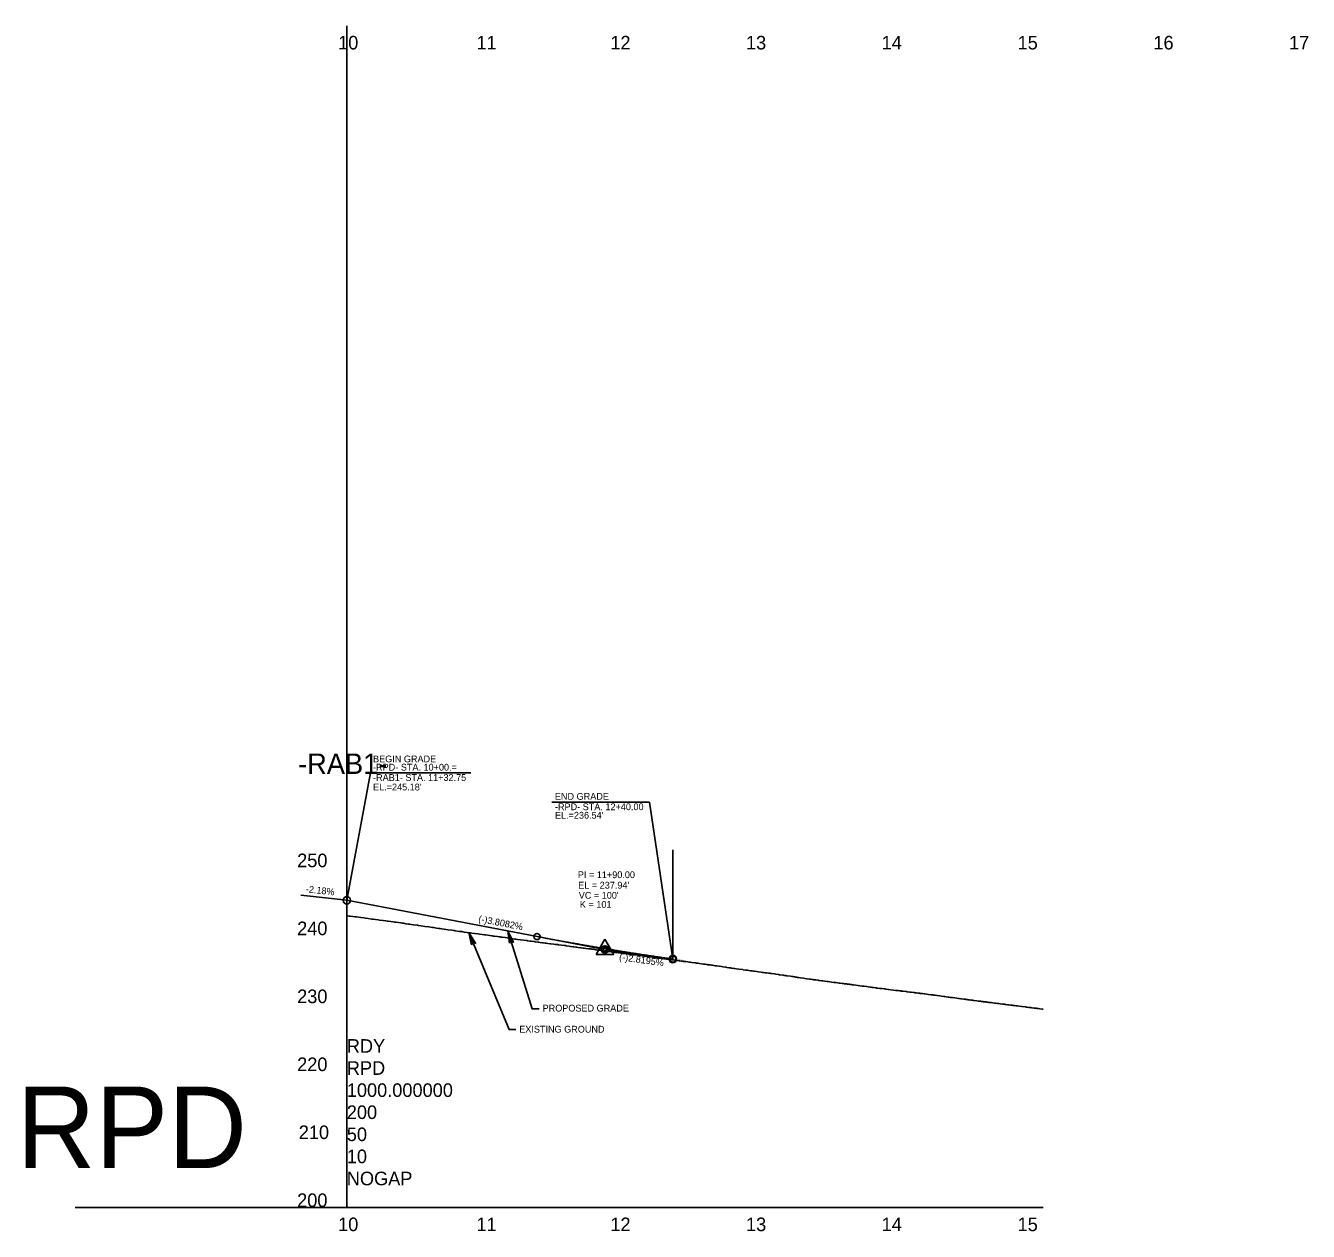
# Model space of a CAD drawing. Extents: x 2115752 to 2121174, y 562881 to 567245.
# Drawn here: x 2116460 to 2117404, y 562881 to 563768 of the extents above; entities that cross this region are included whole.
import ezdxf

# ---------------------------------------------------------------- set-up
doc = ezdxf.new("R2010")
doc.units = 0
for name, color, linetype in [('Exist Profile Cell', 7, 'Continuous'), ('Exist Vertical Profile Ground Line', 7, 'Continuous'), ('Exist Vertical Profile Horizontal Axis Label Major', 7, 'Continuous'), ('Exist Vertical Profile Vertical Axis Label', 7, 'Continuous'), ('Prop PFL VPI Symbol CELL', 7, 'Continuous'), ('Prop Terminator CELL', 7, 'Continuous'), ('Prop Vertical Profile Curve Label', 7, 'Continuous'), ('Prop Vertical Profile Grade', 7, 'Continuous'), ('Prop Vertical Profile Grade Label', 7, 'Continuous'), ('Prop VPI Label', 7, 'Continuous'), ('Scratch_Level_1', 7, 'Continuous')]:
    doc.layers.add(name, color=color, linetype=linetype)

msp = doc.modelspace()

# ---------------------------------------------------------------- linework, layer by layer
at = {"layer": 'Exist Profile Cell'}
for q in [(2116696.3, 563148.24), (2117208.79, 562898.24), (2116696.3, 562898.24)]:
    msp.add_line((2116696.3, 562898.24), q, dxfattribs=at)
at = {"layer": 'Exist Vertical Profile Ground Line'}
for points in [[(2116696.3, 563112.69), (2116696.97, 563112.62), (2116697.97, 563112.52), (2116698.83, 563112.41), (2116700.77, 563112.23), (2116702.56, 563112.03), (2116703.55, 563111.93), (2116706.51, 563111.61), (2116709.14, 563111.23), (2116710.02, 563111.11), (2116712.1, 563110.81), (2116714.73, 563110.39), (2116715.61, 563110.24), (2116717.51, 563109.95), (2116719.34, 563109.69), (2116720.3, 563109.56), (2116723.09, 563109.2), (2116724.94, 563108.97), (2116725.89, 563108.85), (2116726.81, 563108.74), (2116728.68, 563108.51), (2116730.53, 563108.25), (2116731.47, 563108.13), (2116732.38, 563108.01), (2116734.26, 563107.76), (2116736.13, 563107.48), (2116737.06, 563107.35), (2116737.99, 563107.22), (2116739.85, 563106.95), (2116741.71, 563106.69), (2116742.64, 563106.56), (2116743.59, 563106.42), (2116745.45, 563106.15), (2116748.23, 563105.75), (2116749.17, 563105.62), (2116751.07, 563105.35), (2116753.81, 563104.96), (2116756.65, 563104.56), (2116759.4, 563104.17), (2116760.35, 563104.03), (2116762.29, 563103.75), (2116764.1, 563103.49), (2116764.98, 563103.36), (2116765.96, 563103.21), (2116767.97, 563102.93), (2116770.57, 563102.54), (2116773.49, 563102.11), (2116775.28, 563101.86), (2116776.15, 563101.73), (2116779.14, 563101.31), (2116780.86, 563101.08), (2116781.74, 563100.95), (2116782.74, 563100.81), (2116784.79, 563100.52), (2116787.32, 563100.18), (2116788.33, 563100.04), (2116790.4, 563099.75), (2116792.91, 563099.41), (2116793.93, 563099.27), (2116795.99, 563098.99), (2116797.65, 563098.75), (2116798.49, 563098.63), (2116801.56, 563098.21), (2116803.25, 563097.98), (2116804.07, 563097.86), (2116805.11, 563097.72), (2116807.2, 563097.42), (2116808.84, 563097.2), (2116809.66, 563097.08), (2116810.71, 563096.94), (2116812.79, 563096.67), (2116814.44, 563096.44), (2116815.24, 563096.33), (2116817.61, 563096), (2116818.43, 563095.88), (2116820.03, 563095.65), (2116820.83, 563095.54), (2116821.9, 563095.38), (2116824.06, 563095.1), (2116826.42, 563094.79), (2116828.74, 563094.47), (2116829.34, 563094.39), (2116829.65, 563094.35), (2116831.22, 563094.14), (2116832.01, 563094.03), (2116834.27, 563093.74), (2116834.94, 563093.66), (2116835.28, 563093.61), (2116836.81, 563093.42), (2116837.6, 563093.31), (2116838.69, 563093.17), (2116840.37, 563092.96), (2116840.87, 563092.89), (2116842.4, 563092.69), (2116843.16, 563092.6), (2116844.27, 563092.45), (2116845.98, 563092.24), (2116846.49, 563092.17), (2116848.73, 563091.89), (2116849.85, 563091.75), (2116851.72, 563091.51)], [(2116851.72, 563091.51), (2116852.1, 563091.46), (2116854.34, 563091.19), (2116856.6, 563090.91), (2116857.34, 563090.82), (2116857.7, 563090.77), (2116859.95, 563090.44), (2116861.07, 563090.26), (2116862.94, 563089.96), (2116863.34, 563089.9), (2116864.79, 563089.67), (2116865.51, 563089.57), (2116866.64, 563089.41), (2116868.49, 563089.14), (2116868.93, 563089.08), (2116870.35, 563088.92), (2116871.05, 563088.83), (2116872.22, 563088.72), (2116874.09, 563088.54), (2116874.55, 563088.49), (2116875.96, 563088.36), (2116876.67, 563088.28), (2116877.84, 563088.13), (2116879.71, 563087.82), (2116880.17, 563087.76), (2116882.26, 563087.46), (2116884.3, 563087.19), (2116885.03, 563087.09), (2116885.78, 563086.98), (2116887.14, 563086.78), (2116887.45, 563086.73), (2116887.83, 563086.68), (2116889.01, 563086.52), (2116890.88, 563086.25), (2116891.35, 563086.18), (2116892.75, 563086), (2116893.45, 563085.9), (2116893.94, 563085.83), (2116894.61, 563085.74), (2116896.24, 563085.51), (2116896.88, 563085.42), (2116897.19, 563085.38), (2116898.31, 563085.21), (2116899.04, 563085.11), (2116900.43, 563084.92), (2116902.04, 563084.74), (2116902.36, 563084.7), (2116903.68, 563084.55), (2116904.7, 563084.44), (2116907.18, 563084.11), (2116907.8, 563084.03), (2116910.32, 563083.67), (2116913.42, 563083.27), (2116915.96, 563082.94), (2116916.66, 563082.86), (2116919.08, 563082.55), (2116919.91, 563082.44), (2116921.63, 563082.21), (2116922.4, 563082.11), (2116923.15, 563082.02), (2116923.85, 563081.94), (2116924.48, 563081.86), (2116926.1, 563081.65), (2116926.4, 563081.61), (2116927.31, 563081.49), (2116927.95, 563081.4), (2116929.17, 563081.25), (2116929.79, 563081.16), (2116930.11, 563081.12), (2116931.63, 563080.93), (2116932.96, 563080.76), (2116934.4, 563080.57), (2116935.83, 563080.37), (2116936.14, 563080.33), (2116937.64, 563080.13), (2116938.7, 563079.99), (2116939, 563079.94), (2116939.58, 563079.87), (2116940.85, 563079.7), (2116941.52, 563079.61), (2116942.63, 563079.46), (2116943.88, 563079.29), (2116944.38, 563079.22), (2116944.76, 563079.17), (2116945.88, 563079.02), (2116947.26, 563078.83), (2116948.2, 563078.7), (2116949.12, 563078.58), (2116950.31, 563078.42), (2116952.37, 563078.16), (2116952.98, 563078.08), (2116953.7, 563077.99), (2116954.96, 563077.82), (2116955.85, 563077.7), (2116957.37, 563077.48), (2116958.86, 563077.26), (2116960.04, 563077.09), (2116961.03, 563076.94), (2116961.61, 563076.86), (2116962.11, 563076.79), (2116963.73, 563076.56)], [(2116963.73, 563076.56), (2116964.69, 563076.42), (2116965.35, 563076.32), (2116966.55, 563076.15), (2116967.38, 563076.03), (2116968.6, 563075.85), (2116970.26, 563075.61), (2116972.01, 563075.35), (2116973.17, 563075.2), (2116975.09, 563074.93), (2116975.67, 563074.85), (2116976.06, 563074.79), (2116977.61, 563074.57), (2116978.33, 563074.47), (2116978.95, 563074.38), (2116979.29, 563074.32), (2116979.9, 563074.24), (2116981.16, 563074.04), (2116981.87, 563073.94), (2116982.97, 563073.78), (2116984.94, 563073.51), (2116987.68, 563073.14), (2116988.07, 563073.08), (2116989.64, 563072.86), (2116990.57, 563072.73), (2116991.32, 563072.63), (2116992.1, 563072.53), (2116993.5, 563072.34), (2116993.86, 563072.29), (2116994.56, 563072.19), (2116995.75, 563072.02), (2116996.44, 563071.93), (2116997.81, 563071.75), (2116999.4, 563071.53), (2117001.19, 563071.29), (2117002.32, 563071.14), (2117003, 563071.05), (2117004.3, 563070.87), (2117004.87, 563070.79), (2117005.27, 563070.73), (2117006.95, 563070.51), (2117007.55, 563070.43), (2117008.49, 563070.3), (2117008.98, 563070.24), (2117010.79, 563069.99), (2117011.13, 563069.94), (2117012.08, 563069.81), (2117013.7, 563069.59), (2117014.11, 563069.53), (2117014.82, 563069.43), (2117017.49, 563069.05), (2117018.29, 563068.94), (2117019.36, 563068.79), (2117019.99, 563068.7), (2117020.53, 563068.62), (2117022.88, 563068.27), (2117023.78, 563068.13), (2117024.75, 563067.99), (2117025.89, 563067.81), (2117026.59, 563067.69), (2117027.02, 563067.63), (2117027.62, 563067.54), (2117028.38, 563067.42), (2117028.89, 563067.35), (2117030.27, 563067.14), (2117032.37, 563066.84), (2117033.51, 563066.67), (2117034.82, 563066.48), (2117036.76, 563066.21), (2117037.36, 563066.12), (2117037.77, 563066.06), (2117039.23, 563065.85), (2117040.01, 563065.75), (2117041.08, 563065.6), (2117041.52, 563065.54), (2117043.25, 563065.31), (2117043.76, 563065.24), (2117045.85, 563064.97), (2117046.73, 563064.86), (2117048.25, 563064.65), (2117049.81, 563064.45), (2117050.12, 563064.4), (2117050.6, 563064.35), (2117052.99, 563064.03), (2117054.89, 563063.78), (2117055.45, 563063.7), (2117055.8, 563063.66), (2117056.24, 563063.6), (2117057.53, 563063.43), (2117058.78, 563063.26), (2117059.48, 563063.17), (2117060.83, 563063), (2117061.81, 563062.87), (2117062.73, 563062.75), (2117064.03, 563062.58), (2117064.91, 563062.47), (2117065.97, 563062.33), (2117066.75, 563062.23), (2117067.88, 563062.08), (2117068.42, 563062.01), (2117069.22, 563061.9)], [(2117069.22, 563061.9), (2117070.91, 563061.68), (2117072.72, 563061.44), (2117073.92, 563061.28), (2117075.71, 563061.04), (2117077.06, 563060.87), (2117078.96, 563060.61), (2117079.98, 563060.48), (2117081.44, 563060.29), (2117082.2, 563060.2), (2117083.06, 563060.08), (2117084.21, 563059.92), (2117085.45, 563059.77), (2117086.09, 563059.69), (2117086.77, 563059.61), (2117088.69, 563059.36), (2117089.14, 563059.3), (2117089.56, 563059.24), (2117090.14, 563059.18), (2117092.23, 563058.91), (2117093.17, 563058.79), (2117094.44, 563058.64), (2117095.33, 563058.53), (2117096.78, 563058.35), (2117098.76, 563058.11), (2117100.39, 563057.9), (2117101.68, 563057.74), (2117102.15, 563057.68), (2117103.11, 563057.57), (2117104, 563057.47), (2117104.62, 563057.38), (2117104.92, 563057.34), (2117105.74, 563057.24), (2117107.74, 563057), (2117108.17, 563056.95), (2117108.66, 563056.9), (2117110.82, 563056.65), (2117111.58, 563056.56), (2117113.84, 563056.28), (2117114.7, 563056.17), (2117115.74, 563056.03), (2117116.96, 563055.87), (2117117.91, 563055.75), (2117118.25, 563055.7), (2117120.09, 563055.47), (2117121.15, 563055.33), (2117121.83, 563055.24), (2117123.28, 563055.06), (2117124.4, 563054.91), (2117126.3, 563054.66), (2117127.19, 563054.54), (2117127.64, 563054.48), (2117128.27, 563054.4), (2117129.45, 563054.25), (2117130.89, 563054.06), (2117132.69, 563053.81), (2117134.14, 563053.62), (2117135.74, 563053.41), (2117136.55, 563053.3), (2117137.38, 563053.19), (2117138.85, 563052.98), (2117139.64, 563052.88), (2117140.73, 563052.73), (2117141.52, 563052.63), (2117142.09, 563052.55), (2117143.87, 563052.31), (2117145.2, 563052.13), (2117146.43, 563051.97), (2117147.12, 563051.88), (2117148.36, 563051.71), (2117148.86, 563051.65), (2117150.36, 563051.45), (2117151.56, 563051.29), (2117152.14, 563051.21), (2117152.87, 563051.12), (2117153.61, 563051.02), (2117154.69, 563050.88), (2117155.66, 563050.75), (2117156.95, 563050.59), (2117157.52, 563050.51), (2117157.97, 563050.46), (2117160.1, 563050.18), (2117161.02, 563050.06), (2117162.82, 563049.84), (2117163.35, 563049.77), (2117164.36, 563049.63), (2117165.04, 563049.55), (2117166.59, 563049.35), (2117167.44, 563049.25), (2117168.11, 563049.16), (2117168.94, 563049.06), (2117169.84, 563048.94), (2117170.69, 563048.84), (2117171.69, 563048.71), (2117173.09, 563048.53), (2117173.49, 563048.48), (2117173.89, 563048.43), (2117175.27, 563048.26), (2117176.33, 563048.12), (2117177.12, 563048.02), (2117178.86, 563047.8)], [(2117178.86, 563047.8), (2117179.58, 563047.71), (2117180.34, 563047.62), (2117181.02, 563047.53), (2117182.82, 563047.3), (2117183.49, 563047.22), (2117184.84, 563047.05), (2117186.07, 563046.9), (2117186.81, 563046.8), (2117187.68, 563046.69), (2117188.78, 563046.56), (2117189.49, 563046.47), (2117190.06, 563046.4), (2117191.3, 563046.24), (2117193.26, 563046), (2117195.81, 563045.69), (2117196.56, 563045.59), (2117198.37, 563045.36), (2117199.05, 563045.27), (2117199.83, 563045.17), (2117200.56, 563045.08), (2117202.3, 563044.87), (2117203.1, 563044.77), (2117203.65, 563044.7), (2117204.34, 563044.62), (2117205.54, 563044.47), (2117206.38, 563044.37), (2117208.19, 563044.14), (2117208.79, 563044.06)]]:
    msp.add_lwpolyline(points, dxfattribs=at)
at = {"layer": 'Prop PFL VPI Symbol CELL'}
for p, q in [((2116886.3, 563095.45), (2116879.85, 563084.25)), ((2116886.3, 563095.45), (2116892.8, 563084.25)), ((2116879.85, 563084.25), (2116892.8, 563084.25))]:
    msp.add_line(p, q, dxfattribs=at)
for radius in [1.75, 1.2]:
    msp.add_circle((2116886.3, 563087.97), radius, dxfattribs=at)
at = {"layer": 'Prop Terminator CELL'}
for points in [[(2116788.13, 563091.44), (2116786.1, 563100.34), (2116791.05, 563092.61), (2116789.14, 563093.05)], [(2116816.01, 563092.53), (2116814.81, 563101.58), (2116819.04, 563093.42), (2116817.16, 563094.04)]]:
    msp.add_lwpolyline(points, close=True, dxfattribs=at)
at = {"layer": 'Prop Vertical Profile Curve Label'}
for centre in [(2116836.3, 563097.49), (2116936.3, 563080.92)]:
    msp.add_circle(centre, 2.25, dxfattribs=at)
at = {"layer": 'Prop Vertical Profile Grade'}
msp.add_line((2116696.3, 563124.14), (2116836.3, 563097.49), dxfattribs=at)
msp.add_spline([(2116836.3, 563097.49), (2116838.3, 563097.11), (2116840.3, 563096.73), (2116842.3, 563096.35), (2116844.3, 563095.98), (2116846.3, 563095.61), (2116848.3, 563095.24), (2116850.3, 563094.87), (2116852.3, 563094.5), (2116854.3, 563094.14), (2116856.3, 563093.78), (2116858.3, 563093.42), (2116860.3, 563093.06), (2116862.3, 563092.7), (2116864.3, 563092.35), (2116866.3, 563092), (2116868.3, 563091.65), (2116870.3, 563091.3), (2116872.3, 563090.95), (2116874.3, 563090.61), (2116876.3, 563090.27), (2116878.3, 563089.93), (2116880.3, 563089.59), (2116882.3, 563089.25), (2116884.3, 563088.92), (2116886.3, 563088.59), (2116888.3, 563088.25), (2116890.3, 563087.93), (2116892.3, 563087.6), (2116894.3, 563087.28), (2116896.3, 563086.95), (2116898.3, 563086.63), (2116900.3, 563086.31), (2116902.3, 563086), (2116904.3, 563085.68), (2116906.3, 563085.37), (2116908.3, 563085.06), (2116910.3, 563084.75), (2116912.3, 563084.44), (2116914.3, 563084.14), (2116916.3, 563083.84), (2116918.3, 563083.54), (2116920.3, 563083.24), (2116922.3, 563082.94), (2116924.3, 563082.65), (2116926.3, 563082.35), (2116928.3, 563082.06), (2116930.3, 563081.77), (2116932.3, 563081.49), (2116934.3, 563081.2), (2116936.3, 563080.92)], degree=3, dxfattribs=at)
at = {"layer": 'Prop VPI Label'}
for p, q in [((2116696.3, 563124.14), (2116713.85, 563217.95)), ((2116713.85, 563217.95), (2116787.54, 563217.95)), ((2116847.24, 563196.4), (2116919.17, 563196.4)), ((2116936.3, 563080.92), (2116919.17, 563196.4)), ((2116696.3, 563124.14), (2116662.36, 563127.88)), ((2116836.3, 563097.49), (2116883.6, 563088.48)), ((2116936.3, 563080.92), (2116889.03, 563087.58))]:
    msp.add_line(p, q, dxfattribs=at)
for points in [[(2116820.78, 563029.04), (2116815.81, 563029.04), (2116786.1, 563100.34)], [(2116838, 563044.41), (2116832.7, 563044.41), (2116814.81, 563101.58)]]:
    msp.add_lwpolyline(points, dxfattribs=at)
for centre in [(2116696.3, 563124.14), (2116886.3, 563087.97), (2116936.3, 563080.92)]:
    msp.add_circle(centre, 2.75, dxfattribs=at)
at = {"layer": 'Scratch_Level_1'}
for p, q in [((2116696.3, 562898.24), (2116696.3, 563767.63)), ((2116936.3, 563080.31), (2116936.3, 563161.3)), ((2116936.3, 563080.31), (2116942.63, 563079.46)), ((2116696.3, 562898.24), (2116496.27, 562898.24))]:
    msp.add_line(p, q, dxfattribs=at)

# ---------------------------------------------------------------- texts
at = {"layer": 'Exist Profile Cell'}
for s, p in [('RDY', (2116696.3, 563011.99)), ('RPD', (2116696.3, 562995.74)), ('1000.000000', (2116696.3, 562979.49)), ('200', (2116696.3, 562963.24)), ('50', (2116696.3, 562946.99)), ('10', (2116696.3, 562930.74)), ('NOGAP', (2116696.3, 562914.49))]:
    msp.add_text(s, height=10, dxfattribs=at).set_placement(p)
at = {"layer": 'Exist Vertical Profile Horizontal Axis Label Major'}
for s, p in [('10', (2116689.89, 563750.13)), ('11', (2116791.73, 563750.13)), ('12', (2116890.28, 563750.13)), ('13', (2116990.11, 563750.13)), ('14', (2117089.95, 563750.13)), ('15', (2117190.04, 563750.13)), ('16', (2117289.99, 563750.13)), ('17', (2117389.84, 563750.13)), ('10', (2116689.89, 562880.74)), ('11', (2116791.73, 562880.74)), ('12', (2116890.28, 562880.74)), ('13', (2116990.11, 562880.74)), ('14', (2117089.95, 562880.74)), ('15', (2117190.04, 562880.74))]:
    msp.add_text(s, height=10, dxfattribs=at).set_placement(p)
at = {"layer": 'Exist Vertical Profile Vertical Axis Label'}
for s, height, p in [('250', 10, (2116659.74, 563148.49)), ('240', 10, (2116659.74, 563098.49)), ('230', 10, (2116659.74, 563048.49)), ('220', 10, (2116659.74, 562998.49)), ('RPD', 60, (2116453.33, 562927.13)), ('210', 10, (2116660.93, 562948.49)), ('200', 10, (2116659.74, 562898.49))]:
    msp.add_text(s, height=height, dxfattribs=at).set_placement(p)
at = {"layer": 'Prop Vertical Profile Curve Label'}
for s, p in [("VC = 100'", (2116867.03, 563125.32)), ('K = 101', (2116867.87, 563118.64))]:
    msp.add_text(s, height=5, dxfattribs=at).set_placement(p)
at = {"layer": 'Prop Vertical Profile Grade Label'}
for s, rotation, p in [('-2.18%', 353.71635, (2116665.95, 563130.05)), ('(-)3.8082%', 349.21943, (2116792.84, 563108.28)), ('(-)2.8195%', 351.97551, (2116896.52, 563080.21))]:
    msp.add_text(s, height=5, rotation=rotation, dxfattribs=at).set_placement(p)
at = {"layer": 'Prop VPI Label'}
for s, p in [('-RPD- STA. 10+00.=', (2116715.62, 563219.56)), ('BEGIN GRADE', (2116715.62, 563225.66)), ('-RAB1- STA. 11+32.75', (2116715.62, 563211.97)), ("EL.=245.18'", (2116715.62, 563204.97)), ('-RPD- STA. 12+40.00', (2116849.51, 563190.46)), ('END GRADE', (2116849.47, 563198.1)), ("EL.=236.54'", (2116849.51, 563184.21)), ('PI = 11+90.00', (2116866.39, 563140.46)), ("EL = 237.94'", (2116866.64, 563132.76)), ('PROPOSED GRADE', (2116840.42, 563042.31)), ('EXISTING GROUND', (2116823.22, 563026.8))]:
    msp.add_text(s, height=5, dxfattribs=at).set_placement(p)
at = {"layer": 'Scratch_Level_1'}
msp.add_text('-RAB1-', height=15, dxfattribs=at).set_placement((2116660.4, 563217.13))
msp.add_text('-2.6915 %', height=1, rotation=352.33537, dxfattribs=at).set_placement((2116936.82, 563080.66))

doc.saveas('drawing.dxf')
